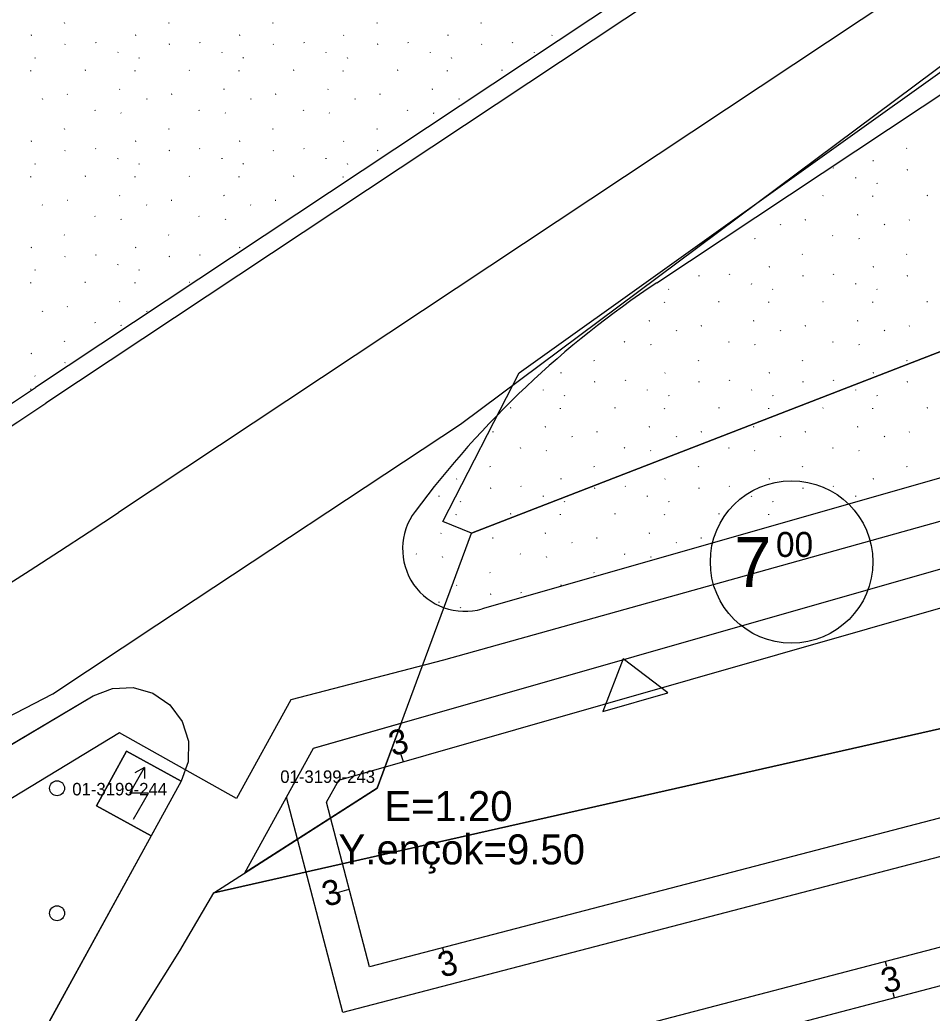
# Model space of a CAD drawing. Extents: x 419396 to 421519, y 4453567 to 4456767.
# Drawn here: x 420781.5 to 420854.5, y 4454894.4 to 4454973.9 of the extents above; entities that cross this region are included whole.
import ezdxf

# ---------------------------------------------------------------- set-up
doc = ezdxf.new("R2010")
doc.units = 0
for name, color, linetype in [('0_KADASTRO', 7, 'Continuous'), ('0_PLAN_ONAMA_İLAVE_SINIRI', 7, 'Continuous'), ('Level 16', 7, 'Continuous'), ('Level 20', 7, 'Continuous'), ('Level 22', 7, 'Continuous'), ('Level 28', 7, 'Continuous'), ('Level 29', 7, 'Continuous'), ('Level 30', 7, 'Continuous'), ('Level 41', 7, 'Continuous'), ('Level 47', 7, 'Continuous'), ('Level 54', 7, 'Continuous'), ('Level 57', 7, 'Continuous'), ('Level 58', 7, 'Continuous'), ('Level 62', 7, 'Continuous')]:
    doc.layers.add(name, color=color, linetype=linetype)

msp = doc.modelspace()

# ---------------------------------------------------------------- linework, layer by layer
at = {"layer": '0_KADASTRO'}
for points in [[(420815.335, 4454933.733), (420821.44, 4454945.63), (420857.72, 4454971.51), (420910.15, 4455007.94), (420919.031, 4455014.756), (420941.72, 4455028.89), (420964.28, 4455044.57), (420996.886, 4455065.718), (420998.28, 4455041.22), (421001.29, 4455023.78), (420999.84, 4455016), (420988.55, 4455008.8), (420981.083, 4454995.989), (420959.673, 4454987.834), (420817.618, 4454932.806)], [(420799.505, 4454905.613), (420804.985, 4454915.585), (420811.99, 4454917.591), (420810.07, 4454912.4)], [(420787.621, 4454910.982), (420790.029, 4454915.364), (420794.411, 4454912.956), (420792.003, 4454908.574)]]:
    msp.add_lwpolyline(points, close=True, dxfattribs=at)
for points in [[(420937.4, 4454937.02), (420926.58, 4454934.69), (420920.8, 4454933.38), (420919.1, 4454932.94), (420912.48, 4454931.32), (420909.81, 4454930.61), (420899.99, 4454928.24), (420897.51, 4454927.64), (420894.4, 4454926.97), (420890.25, 4454925.79), (420880.57, 4454923.47), (420873.09, 4454921.23), (420867.5, 4454919.92), (420865.82, 4454919.51), (420865.31, 4454919.42), (420862.53, 4454918.75), (420861.44, 4454918.57), (420797.01, 4454904.01), (420810.07, 4454912.4), (420817.618, 4454932.806), (420959.673, 4454987.834)], [(420771, 4454862.22), (420794.29, 4454899.38), (420797.01, 4454904.01), (420861.44, 4454918.57), (420862.53, 4454918.75), (420865.31, 4454919.42), (420865.82, 4454919.51), (420867.5, 4454919.92), (420873.09, 4454921.23), (420880.57, 4454923.47), (420890.25, 4454925.79), (420894.4, 4454926.97), (420897.51, 4454927.64), (420899.99, 4454928.24), (420909.81, 4454930.61), (420912.48, 4454931.32), (420919.1, 4454932.94), (420920.8, 4454933.38), (420926.58, 4454934.69), (420937.4, 4454937.02)], [(420635.208, 4454857.612), (420730.894, 4454888.765), (420737.737, 4454891.311), (420742.173, 4454893.319), (420744.347, 4454894.413), (420746.491, 4454895.568), (420748.602, 4454896.781), (420787.366, 4454919.774), (420788.903, 4454920.374), (420790.55, 4454920.45), (420792.136, 4454919.994), (420793.492, 4454919.055), (420794.475, 4454917.73), (420794.983, 4454916.161), (420794.961, 4454914.511), (420794.411, 4454912.956), (420790.029, 4454915.364), (420787.621, 4454910.982), (420792.003, 4454908.574), (420755.345, 4454841.869), (420759.828, 4454824.618)]]:
    msp.add_lwpolyline(points, dxfattribs=at)
at = {"layer": '0_PLAN_ONAMA_İLAVE_SINIRI'}
msp.add_lwpolyline([(420908.632, 4454948.702), (420815.388, 4454922.641), (420803.182, 4454919.474), (420798.827, 4454911.556), (420789.458, 4454916.834), (420744.063, 4454889.254), (420733.169, 4454885.933)], dxfattribs=at)
at = {"layer": 'Level 16'}
for p, q in [((420829.756, 4454922.732), (420828.148, 4454918.529)), ((420833.341, 4454920.012), (420829.756, 4454922.732)), ((420828.148, 4454918.529), (420833.341, 4454920.012))]:
    msp.add_line(p, q, dxfattribs=at)
at = {"layer": 'Level 20'}
for p, q in [((420807.013, 4454913.046), (420906.461, 4454941.519)), ((420911.107, 4454924.636), (420809.471, 4454898.1)), ((420811.973, 4454915.091), (420812.151, 4454914.517)), ((420806.035, 4454911.266), (420807.013, 4454913.046)), ((420788.391, 4454879.16), (420914.557, 4454912.101)), ((420809.471, 4454898.1), (420806.035, 4454911.266)), ((420806.909, 4454904.036), (420807.85, 4454904.31)), ((420815.3, 4454899.622), (420815.45, 4454899.109)), ((420850.716, 4454898.533), (420850.817, 4454898.146)), ((420851.474, 4454895.63), (420851.373, 4454896.017))]:
    msp.add_line(p, q, dxfattribs=at)
at = {"layer": 'Level 22'}
for p, q in [((420816.76, 4454941.507), (420858.075, 4454972.344)), ((420792.452, 4454925.451), (420816.76, 4454941.507)), ((420784.126, 4454919.951), (420792.452, 4454925.451)), ((420759.876, 4454907.377), (420784.126, 4454919.951))]:
    msp.add_line(p, q, dxfattribs=at)
at = {"layer": 'Level 28'}
for p, q in [((420787.621, 4454910.982), (420790.029, 4454915.364)), ((420790.029, 4454915.364), (420794.411, 4454912.956)), ((420802.831, 4454911.664), (420804.985, 4454915.584)), ((420790.289, 4454911.991), (420791.481, 4454914.055)), ((420794.411, 4454912.956), (420792.003, 4454908.574)), ((420794.109, 4454912.407), (420755.345, 4454841.869)), ((420791.776, 4454911.991), (420790.289, 4454911.991)), ((420790.586, 4454909.926), (420791.776, 4454911.991)), ((420807.327, 4454894.439), (420802.831, 4454911.664)), ((420792.003, 4454908.574), (420787.621, 4454910.982))]:
    msp.add_line(p, q, dxfattribs=at)
for points in [[(420791.481, 4454914.055), (420790.706, 4454913.607)], [(420791.481, 4454914.055), (420791.481, 4454913.163)]]:
    msp.add_lwpolyline(points, dxfattribs=at)
at = {"layer": 'Level 29'}
for p, q in [((420804.985, 4454915.584), (420908.548, 4454945.237)), ((420914.805, 4454922.5), (420807.327, 4454894.439)), ((420786.383, 4454881.736), (420916.663, 4454915.751))]:
    msp.add_line(p, q, dxfattribs=at)
at = {"layer": 'Level 41'}
for p, q in [((420785.053, 4454973.65), (420785.081, 4454973.607)), ((420793.386, 4454973.65), (420793.414, 4454973.607)), ((420801.718, 4454973.65), (420801.746, 4454973.607)), ((420810.05, 4454973.65), (420810.078, 4454973.607)), ((420818.382, 4454973.65), (420818.41, 4454973.607)), ((420826.714, 4454973.65), (420826.729, 4454973.628)), ((420782.432, 4454972.637), (420782.385, 4454972.614)), ((420790.764, 4454972.637), (420790.718, 4454972.614)), ((420799.097, 4454972.637), (420799.05, 4454972.614)), ((420807.429, 4454972.637), (420807.382, 4454972.614)), ((420815.761, 4454972.637), (420815.714, 4454972.614)), ((420824.093, 4454972.637), (420824.046, 4454972.614)), ((420785.135, 4454971.908), (420785.088, 4454971.885)), ((420787.544, 4454972.071), (420787.572, 4454972.027)), ((420793.467, 4454971.908), (420793.421, 4454971.885)), ((420795.876, 4454972.071), (420795.904, 4454972.027)), ((420801.8, 4454971.908), (420801.753, 4454971.885)), ((420804.208, 4454972.071), (420804.236, 4454972.027)), ((420810.132, 4454971.908), (420810.085, 4454971.885)), ((420812.54, 4454972.071), (420812.568, 4454972.027)), ((420818.464, 4454971.908), (420818.417, 4454971.885)), ((420820.873, 4454972.071), (420820.901, 4454972.027)), ((420789.343, 4454971.242), (420789.351, 4454971.293)), ((420797.676, 4454971.242), (420797.683, 4454971.293)), ((420806.008, 4454971.242), (420806.015, 4454971.293)), ((420814.34, 4454971.242), (420814.347, 4454971.293)), ((420822.672, 4454971.242), (420822.68, 4454971.293)), ((420782.685, 4454970.856), (420782.713, 4454970.813)), ((420791.017, 4454970.856), (420791.045, 4454970.813)), ((420799.349, 4454970.856), (420799.377, 4454970.813)), ((420807.681, 4454970.856), (420807.709, 4454970.813)), ((420816.013, 4454970.856), (420816.041, 4454970.813)), ((420782.378, 4454969.769), (420782.385, 4454969.82)), ((420786.745, 4454969.843), (420786.698, 4454969.82)), ((420790.71, 4454969.769), (420790.718, 4454969.82)), ((420795.077, 4454969.843), (420795.03, 4454969.82)), ((420799.042, 4454969.769), (420799.05, 4454969.82)), ((420803.409, 4454969.843), (420803.362, 4454969.82)), ((420807.374, 4454969.769), (420807.382, 4454969.82)), ((420811.741, 4454969.843), (420811.695, 4454969.82)), ((420815.707, 4454969.769), (420815.714, 4454969.82)), ((420820.074, 4454969.843), (420820.027, 4454969.82)), ((420785.317, 4454967.914), (420785.271, 4454967.891)), ((420789.508, 4454968.309), (420789.462, 4454968.286)), ((420793.65, 4454967.914), (420793.603, 4454967.891)), ((420797.841, 4454968.309), (420797.794, 4454968.286)), ((420801.982, 4454967.914), (420801.935, 4454967.891)), ((420806.173, 4454968.309), (420806.126, 4454968.286)), ((420810.314, 4454967.914), (420810.267, 4454967.891)), ((420814.505, 4454968.309), (420814.458, 4454968.286)), ((420783.292, 4454967.561), (420783.32, 4454967.517)), ((420791.624, 4454967.561), (420791.652, 4454967.517)), ((420799.956, 4454967.561), (420799.984, 4454967.517)), ((420808.288, 4454967.561), (420808.317, 4454967.517)), ((420816.621, 4454967.561), (420816.649, 4454967.517)), ((420787.489, 4454966.657), (420787.517, 4454966.614)), ((420789.578, 4454966.437), (420789.607, 4454966.393)), ((420795.822, 4454966.657), (420795.85, 4454966.614)), ((420797.911, 4454966.437), (420797.939, 4454966.393)), ((420804.154, 4454966.657), (420804.182, 4454966.614)), ((420806.243, 4454966.437), (420806.271, 4454966.393)), ((420812.486, 4454966.657), (420812.514, 4454966.614)), ((420814.575, 4454966.437), (420814.603, 4454966.393)), ((420785.053, 4454965.161), (420785.081, 4454965.118)), ((420793.386, 4454965.161), (420793.414, 4454965.118)), ((420801.718, 4454965.161), (420801.746, 4454965.118)), ((420810.05, 4454965.161), (420810.078, 4454965.118)), ((420782.432, 4454964.148), (420782.385, 4454964.125)), ((420790.764, 4454964.148), (420790.718, 4454964.125)), ((420799.097, 4454964.148), (420799.05, 4454964.125)), ((420807.429, 4454964.148), (420807.382, 4454964.125)), ((420785.135, 4454963.419), (420785.088, 4454963.396)), ((420787.544, 4454963.582), (420787.572, 4454963.539)), ((420793.467, 4454963.419), (420793.421, 4454963.396)), ((420795.876, 4454963.582), (420795.904, 4454963.539)), ((420801.8, 4454963.419), (420801.753, 4454963.396)), ((420804.208, 4454963.582), (420804.236, 4454963.539)), ((420810.132, 4454963.419), (420810.085, 4454963.396)), ((420852.417, 4454963.611), (420852.445, 4454963.567)), ((420782.685, 4454962.367), (420782.713, 4454962.324)), ((420789.343, 4454962.753), (420789.351, 4454962.804)), ((420791.017, 4454962.367), (420791.045, 4454962.324)), ((420797.676, 4454962.753), (420797.683, 4454962.804)), ((420799.349, 4454962.367), (420799.377, 4454962.324)), ((420806.008, 4454962.753), (420806.015, 4454962.804)), ((420807.681, 4454962.367), (420807.709, 4454962.324)), ((420849.796, 4454962.598), (420849.749, 4454962.575)), ((420846.575, 4454962.032), (420846.603, 4454961.988)), ((420852.499, 4454961.869), (420852.452, 4454961.846)), ((420782.378, 4454961.28), (420782.385, 4454961.331)), ((420786.745, 4454961.354), (420786.698, 4454961.331)), ((420790.71, 4454961.28), (420790.718, 4454961.331)), ((420795.077, 4454961.354), (420795.03, 4454961.331)), ((420799.042, 4454961.28), (420799.05, 4454961.331)), ((420803.409, 4454961.354), (420803.362, 4454961.331)), ((420807.374, 4454961.28), (420807.382, 4454961.331)), ((420848.375, 4454961.203), (420848.382, 4454961.254)), ((420850.048, 4454960.817), (420850.076, 4454960.773)), ((420789.508, 4454959.82), (420789.462, 4454959.797)), ((420797.841, 4454959.82), (420797.794, 4454959.797)), ((420845.776, 4454959.804), (420845.729, 4454959.781)), ((420849.741, 4454959.729), (420849.749, 4454959.781)), ((420854.108, 4454959.804), (420854.062, 4454959.781)), ((420783.292, 4454959.072), (420783.32, 4454959.028)), ((420785.317, 4454959.425), (420785.271, 4454959.402)), ((420791.624, 4454959.072), (420791.652, 4454959.028)), ((420793.65, 4454959.425), (420793.603, 4454959.402)), ((420799.956, 4454959.072), (420799.984, 4454959.028)), ((420801.982, 4454959.425), (420801.935, 4454959.402)), ((420848.54, 4454958.269), (420848.493, 4454958.247)), ((420787.489, 4454958.169), (420787.517, 4454958.125)), ((420789.578, 4454957.948), (420789.607, 4454957.904)), ((420795.822, 4454958.169), (420795.85, 4454958.125)), ((420797.911, 4454957.948), (420797.939, 4454957.904)), ((420842.323, 4454957.522), (420842.351, 4454957.478)), ((420844.349, 4454957.874), (420844.302, 4454957.852)), ((420850.655, 4454957.522), (420850.684, 4454957.478)), ((420852.681, 4454957.874), (420852.634, 4454957.852)), ((420785.053, 4454956.673), (420785.081, 4454956.629)), ((420793.386, 4454956.673), (420793.414, 4454956.629)), ((420838.189, 4454956.618), (420838.217, 4454956.575)), ((420846.521, 4454956.618), (420846.549, 4454956.575)), ((420840.278, 4454956.398), (420840.306, 4454956.354)), ((420848.61, 4454956.398), (420848.638, 4454956.354)), ((420782.432, 4454955.659), (420782.385, 4454955.636)), ((420787.544, 4454955.093), (420787.572, 4454955.05)), ((420790.764, 4454955.659), (420790.718, 4454955.636)), ((420795.876, 4454955.093), (420795.904, 4454955.05)), ((420799.097, 4454955.659), (420799.05, 4454955.636)), ((420844.085, 4454955.122), (420844.113, 4454955.079)), ((420852.417, 4454955.122), (420852.445, 4454955.079)), ((420785.135, 4454954.93), (420785.088, 4454954.907)), ((420789.343, 4454954.264), (420789.351, 4454954.316)), ((420793.467, 4454954.93), (420793.421, 4454954.907)), ((420782.685, 4454953.879), (420782.713, 4454953.835)), ((420791.017, 4454953.879), (420791.045, 4454953.835)), ((420838.243, 4454953.543), (420838.271, 4454953.499)), ((420841.464, 4454954.109), (420841.417, 4454954.086)), ((420846.575, 4454953.543), (420846.603, 4454953.499)), ((420849.796, 4454954.109), (420849.749, 4454954.086)), ((420782.378, 4454952.791), (420782.385, 4454952.842)), ((420786.745, 4454952.865), (420786.698, 4454952.842)), ((420790.71, 4454952.791), (420790.718, 4454952.842)), ((420795.077, 4454952.865), (420795.03, 4454952.842)), ((420835.834, 4454953.38), (420835.788, 4454953.357)), ((420840.043, 4454952.714), (420840.05, 4454952.765)), ((420844.167, 4454953.38), (420844.12, 4454953.357)), ((420848.375, 4454952.714), (420848.382, 4454952.765)), ((420852.499, 4454953.38), (420852.452, 4454953.357)), ((420833.384, 4454952.328), (420833.412, 4454952.285)), ((420841.716, 4454952.328), (420841.744, 4454952.285)), ((420850.048, 4454952.328), (420850.076, 4454952.285)), ((420789.508, 4454951.331), (420789.462, 4454951.308)), ((420833.077, 4454951.241), (420833.085, 4454951.292)), ((420837.444, 4454951.315), (420837.397, 4454951.292)), ((420841.409, 4454951.241), (420841.417, 4454951.292)), ((420845.776, 4454951.315), (420845.729, 4454951.292)), ((420849.741, 4454951.241), (420849.749, 4454951.292)), ((420854.108, 4454951.315), (420854.062, 4454951.292)), ((420783.292, 4454950.583), (420783.32, 4454950.539)), ((420785.317, 4454950.936), (420785.271, 4454950.913)), ((420791.624, 4454950.583), (420791.652, 4454950.539)), ((420787.489, 4454949.68), (420787.517, 4454949.636)), ((420789.578, 4454949.459), (420789.607, 4454949.416)), ((420831.875, 4454949.781), (420831.829, 4454949.758)), ((420840.208, 4454949.781), (420840.161, 4454949.758)), ((420848.54, 4454949.781), (420848.493, 4454949.758)), ((420833.991, 4454949.033), (420834.019, 4454948.989)), ((420836.017, 4454949.386), (420835.97, 4454949.363)), ((420842.323, 4454949.033), (420842.351, 4454948.989)), ((420844.349, 4454949.386), (420844.302, 4454949.363)), ((420850.655, 4454949.033), (420850.684, 4454948.989)), ((420852.681, 4454949.386), (420852.634, 4454949.363)), ((420785.053, 4454948.184), (420785.081, 4454948.14)), ((420829.856, 4454948.129), (420829.884, 4454948.086)), ((420831.945, 4454947.909), (420831.974, 4454947.865)), ((420838.189, 4454948.129), (420838.217, 4454948.086)), ((420840.278, 4454947.909), (420840.306, 4454947.865)), ((420846.521, 4454948.129), (420846.549, 4454948.086)), ((420848.61, 4454947.909), (420848.638, 4454947.865)), ((420782.432, 4454947.17), (420782.385, 4454947.147)), ((420785.135, 4454946.441), (420785.088, 4454946.418)), ((420827.42, 4454946.633), (420827.448, 4454946.59)), ((420835.753, 4454946.633), (420835.781, 4454946.59)), ((420844.085, 4454946.633), (420844.113, 4454946.59)), ((420852.417, 4454946.633), (420852.445, 4454946.59)), ((420824.799, 4454945.62), (420824.752, 4454945.597)), ((420833.131, 4454945.62), (420833.085, 4454945.597)), ((420841.464, 4454945.62), (420841.417, 4454945.597)), ((420849.796, 4454945.62), (420849.749, 4454945.597)), ((420782.685, 4454945.39), (420782.713, 4454945.346)), ((420827.502, 4454944.891), (420827.455, 4454944.868)), ((420829.911, 4454945.054), (420829.939, 4454945.011)), ((420835.834, 4454944.891), (420835.788, 4454944.868)), ((420838.243, 4454945.054), (420838.271, 4454945.011)), ((420844.167, 4454944.891), (420844.12, 4454944.868)), ((420846.575, 4454945.054), (420846.603, 4454945.011)), ((420852.499, 4454944.891), (420852.452, 4454944.868)), ((420782.378, 4454944.302), (420782.385, 4454944.353)), ((420823.378, 4454944.225), (420823.386, 4454944.276)), ((420831.71, 4454944.225), (420831.718, 4454944.276)), ((420840.043, 4454944.225), (420840.05, 4454944.276)), ((420848.375, 4454944.225), (420848.382, 4454944.276)), ((420825.052, 4454943.839), (420825.08, 4454943.796)), ((420833.384, 4454943.839), (420833.412, 4454943.796)), ((420841.716, 4454943.839), (420841.744, 4454943.796)), ((420850.048, 4454943.839), (420850.076, 4454943.796)), ((420820.78, 4454942.826), (420820.733, 4454942.803)), ((420824.745, 4454942.752), (420824.752, 4454942.803)), ((420829.112, 4454942.826), (420829.065, 4454942.803)), ((420833.077, 4454942.752), (420833.085, 4454942.803)), ((420837.444, 4454942.826), (420837.397, 4454942.803)), ((420841.409, 4454942.752), (420841.417, 4454942.803)), ((420845.776, 4454942.826), (420845.729, 4454942.803)), ((420849.741, 4454942.752), (420849.749, 4454942.803)), ((420854.108, 4454942.826), (420854.062, 4454942.803)), ((420819.352, 4454940.897), (420819.305, 4454940.874)), ((420823.543, 4454941.292), (420823.496, 4454941.269)), ((420827.684, 4454940.897), (420827.638, 4454940.874)), ((420831.875, 4454941.292), (420831.829, 4454941.269)), ((420836.017, 4454940.897), (420835.97, 4454940.874)), ((420840.208, 4454941.292), (420840.161, 4454941.269)), ((420844.349, 4454940.897), (420844.302, 4454940.874)), ((420848.54, 4454941.292), (420848.493, 4454941.269)), ((420852.681, 4454940.897), (420852.634, 4454940.874)), ((420825.659, 4454940.544), (420825.687, 4454940.5)), ((420833.991, 4454940.544), (420834.019, 4454940.5)), ((420842.323, 4454940.544), (420842.351, 4454940.5)), ((420850.655, 4454940.544), (420850.684, 4454940.5)), ((420821.524, 4454939.641), (420821.552, 4454939.597)), ((420823.613, 4454939.42), (420823.641, 4454939.376)), ((420829.856, 4454939.641), (420829.884, 4454939.597)), ((420831.945, 4454939.42), (420831.974, 4454939.376)), ((420838.189, 4454939.641), (420838.217, 4454939.597)), ((420840.278, 4454939.42), (420840.306, 4454939.376)), ((420846.521, 4454939.641), (420846.549, 4454939.597)), ((420848.61, 4454939.42), (420848.638, 4454939.376)), ((420819.088, 4454938.145), (420819.116, 4454938.101)), ((420827.42, 4454938.145), (420827.448, 4454938.101)), ((420835.753, 4454938.145), (420835.781, 4454938.101)), ((420844.085, 4454938.145), (420844.113, 4454938.101)), ((420852.417, 4454938.145), (420852.445, 4454938.101)), ((420816.467, 4454937.131), (420816.42, 4454937.108)), ((420824.799, 4454937.131), (420824.752, 4454937.108)), ((420833.131, 4454937.131), (420833.085, 4454937.108)), ((420841.464, 4454937.131), (420841.417, 4454937.108)), ((420849.796, 4454937.131), (420849.749, 4454937.108)), ((420819.17, 4454936.402), (420819.123, 4454936.379)), ((420821.579, 4454936.565), (420821.607, 4454936.522)), ((420827.502, 4454936.402), (420827.455, 4454936.379)), ((420829.911, 4454936.565), (420829.939, 4454936.522)), ((420835.834, 4454936.402), (420835.788, 4454936.379)), ((420838.243, 4454936.565), (420838.271, 4454936.522)), ((420844.167, 4454936.402), (420844.12, 4454936.379)), ((420846.575, 4454936.565), (420846.603, 4454936.522)), ((420815.046, 4454935.736), (420815.053, 4454935.788)), ((420816.719, 4454935.351), (420816.747, 4454935.307)), ((420823.378, 4454935.736), (420823.386, 4454935.788)), ((420825.052, 4454935.351), (420825.08, 4454935.307)), ((420831.71, 4454935.736), (420831.718, 4454935.788)), ((420833.384, 4454935.351), (420833.412, 4454935.307)), ((420840.043, 4454935.736), (420840.05, 4454935.788)), ((420841.716, 4454935.351), (420841.744, 4454935.307)), ((420848.375, 4454935.736), (420848.382, 4454935.788)), ((420816.413, 4454934.263), (420816.42, 4454934.314)), ((420820.78, 4454934.337), (420820.733, 4454934.314)), ((420824.745, 4454934.263), (420824.752, 4454934.314)), ((420829.112, 4454934.337), (420829.065, 4454934.314)), ((420833.077, 4454934.263), (420833.085, 4454934.314)), ((420837.444, 4454934.337), (420837.397, 4454934.314)), ((420841.409, 4454934.263), (420841.417, 4454934.314)), ((420815.211, 4454932.803), (420815.164, 4454932.78)), ((420823.543, 4454932.803), (420823.496, 4454932.78)), ((420831.875, 4454932.803), (420831.829, 4454932.78)), ((420817.327, 4454932.055), (420817.355, 4454932.011)), ((420819.352, 4454932.408), (420819.305, 4454932.385)), ((420825.659, 4454932.055), (420825.687, 4454932.011)), ((420827.684, 4454932.408), (420827.638, 4454932.385)), ((420833.991, 4454932.055), (420834.019, 4454932.011)), ((420836.017, 4454932.408), (420835.97, 4454932.385)), ((420813.192, 4454931.152), (420813.22, 4454931.108)), ((420815.281, 4454930.931), (420815.309, 4454930.888)), ((420821.524, 4454931.152), (420821.552, 4454931.108)), ((420823.613, 4454930.931), (420823.641, 4454930.888)), ((420829.856, 4454931.152), (420829.884, 4454931.108)), ((420831.945, 4454930.931), (420831.974, 4454930.888)), ((420819.088, 4454929.656), (420819.116, 4454929.612)), ((420827.42, 4454929.656), (420827.448, 4454929.612)), ((420816.467, 4454928.642), (420816.42, 4454928.619)), ((420821.579, 4454928.077), (420821.607, 4454928.033)), ((420824.799, 4454928.642), (420824.752, 4454928.619)), ((420815.046, 4454927.248), (420815.053, 4454927.299)), ((420819.17, 4454927.913), (420819.123, 4454927.89)), ((420816.719, 4454926.862), (420816.747, 4454926.818))]:
    msp.add_line(p, q, dxfattribs=at)
at = {"layer": 'Level 47'}
for centre in [(420784.472, 4454912.386), (420784.472, 4454902.386)]:
    msp.add_circle(centre, 0.6, dxfattribs=at)
at = {"layer": 'Level 54'}
for p, q in [((420790.289, 4454911.991), (420791.481, 4454914.055)), ((420791.776, 4454911.991), (420790.289, 4454911.991)), ((420790.586, 4454909.926), (420791.776, 4454911.991))]:
    msp.add_line(p, q, dxfattribs=at)
for points in [[(420791.481, 4454914.055), (420790.706, 4454913.607)], [(420791.481, 4454914.055), (420791.481, 4454913.163)]]:
    msp.add_lwpolyline(points, dxfattribs=at)
at = {"layer": 'Level 57'}
for p, q in [((420787.621, 4454910.982), (420790.029, 4454915.364)), ((420790.029, 4454915.364), (420794.411, 4454912.956)), ((420794.411, 4454912.956), (420792.003, 4454908.574)), ((420792.003, 4454908.574), (420787.621, 4454910.982))]:
    msp.add_line(p, q, dxfattribs=at)
at = {"layer": 'Level 58'}
msp.add_circle((420843.237, 4454930.493), 6.5, dxfattribs=at)
at = {"layer": 'Level 62'}
for p, q in [((420944.215, 4455051.592), (420782.747, 4454944.442)), ((420945.055, 4455050.348), (420783.576, 4454943.192)), ((420902.303, 4455009.377), (420789.382, 4454934.443)), ((420832.458, 4454952.827), (420905.784, 4455001.485)), ((420902.793, 4454950.87), (420818.492, 4454926.734)), ((420787.366, 4454919.774), (420788.903, 4454920.374)), ((420788.903, 4454920.374), (420790.55, 4454920.45)), ((420790.55, 4454920.45), (420792.136, 4454919.994)), ((420748.602, 4454896.781), (420787.366, 4454919.774)), ((420792.136, 4454919.994), (420793.492, 4454919.055)), ((420793.492, 4454919.055), (420794.475, 4454917.73)), ((420794.475, 4454917.73), (420794.983, 4454916.161)), ((420794.983, 4454916.161), (420794.961, 4454914.511)), ((420794.961, 4454914.511), (420794.411, 4454912.956))]:
    msp.add_line(p, q, dxfattribs=at)
for centre, radius, start, end in [((420875.586, 4454887.835), 78, 123.56808, 143.22221), ((420478.637, 4455402.718), 550, 285.74194, 303.56808), ((420478.637, 4455402.718), 551.5, 285.68227, 303.56808), ((420478.637, 4455402.718), 562, 285.2591, 303.56808), ((420817.116, 4454931.541), 5, 143.22221, 285.97692)]:
    msp.add_arc(centre, radius, start, end, dxfattribs=at)

# ---------------------------------------------------------------- texts
at = {"layer": '0_KADASTRO'}
for s, p in [('01-3199-243', (420802.329, 4454912.814)), ('01-3199-244', (420785.691, 4454911.815))]:
    msp.add_text(s, height=1, dxfattribs=at).set_placement(p)
at = {"layer": 'Level 20'}
for rotation, p in [(14.63268, (420811.308, 4454914.939)), (14.63268, (420805.966, 4454902.891)), (14.63268, (420815.244, 4454897.22)), (14.63267, (420850.703, 4454895.946))]:
    msp.add_text('3', height=2, rotation=rotation, dxfattribs=at).set_placement(p)
at = {"layer": 'Level 30'}
for s, p in [('E=1.20', (420810.653, 4454909.758)), ('Y.ençok=9.50', (420806.99, 4454906.294))]:
    msp.add_text(s, height=2.4, dxfattribs=at).set_placement(p)
at = {"layer": 'Level 58'}
for s, height, p in [('00', 1.9983, (420841.988, 4454930.892)), ('7', 3.997, (420838.641, 4454928.494))]:
    msp.add_text(s, height=height, dxfattribs=at).set_placement(p)

doc.saveas('drawing.dxf')
